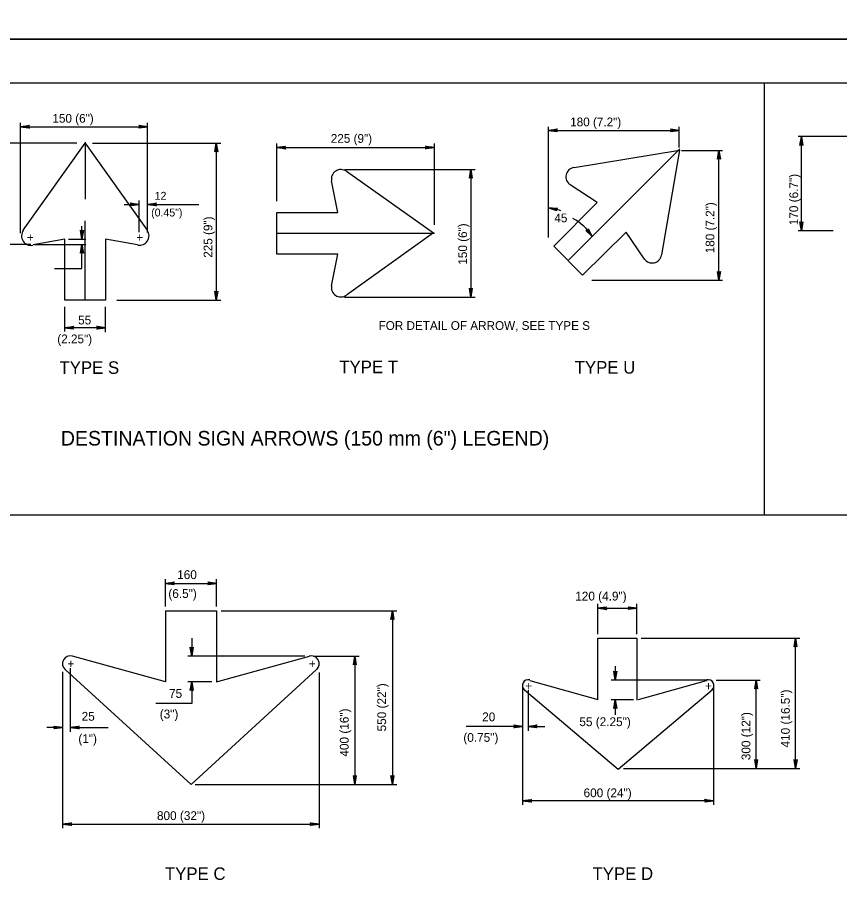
# Model space of a CAD drawing. Extents: x 637580 to 641849, y 297270 to 299646.
# Drawn here: x 641247.2 to 641528.9, y 298762.6 to 299059.1 of the extents above; entities that cross this region are included whole.
import ezdxf

# ---------------------------------------------------------------- set-up
doc = ezdxf.new("R2010")
doc.units = 0
for name, color, linetype in [('1', 7, 'Continuous'), ('2', 7, 'Continuous'), ('3', 7, 'Continuous'), ('XCS-GRID-HVGL', 7, 'Continuous')]:
    doc.layers.add(name, color=color, linetype=linetype)

# ---------------------------------------------------------------- blocks, each defined once
blk = doc.blocks.new('RARROW')
at = {"layer": '3'}
blk.add_lwpolyline([(-2.2695, 0.285), (-2.184875, 0.12075), (0, 0), (-2.2695, 0.285), (-2.38575, 0.384625), (0, 0), (-2.183125, -0.108), (-2.262875, -0.2705), (0, 0), (-2.38575, -0.379125), (-2.262875, -0.2705)], dxfattribs=at)

msp = doc.modelspace()

# ---------------------------------------------------------------- linework, layer by layer
at = {"layer": '1'}
msp.add_line((640984.31, 299036.63), (641770.31, 299036.63), dxfattribs=at)
for points in [[(641503.19, 298888.5), (641503.19, 299036.63)], [(641770.31, 298888.5), (640984.31, 298888.5)]]:
    msp.add_lwpolyline(points, dxfattribs=at)
at = {"layer": '2'}
for p, q in [((641248.31, 298985.13), (641248.31, 299023)), ((641248.31, 299021.63), (641291.81, 299021.63)), ((641291.81, 298985.38), (641291.81, 299023)), ((641429.19, 298983.63), (641429.19, 299021.63)), ((641473.94, 299014.5), (641473.94, 299021.63)), ((641429.19, 299020.38), (641473.94, 299020.38)), ((641549.69, 299018.25), (641514.69, 299018.25)), ((641515.81, 298986), (641515.81, 299018.25)), ((641267.56, 299016), (641235.44, 299016)), ((641249.19, 298986.13), (641270.44, 299016)), ((641270.44, 299016.38), (641270.44, 298996.75)), ((641270.44, 299016), (641270.44, 299016)), ((641270.44, 299016), (641291.69, 298986.13)), ((641272.94, 299016), (641316.94, 299016)), ((641315.33, 299016), (641315.33, 298962.25)), ((641336.06, 298996.13), (641336.06, 299015.88)), ((641390.06, 298988), (641390.06, 299015.88)), ((641336.06, 299014.5), (641390.06, 299014.5)), ((641435.94, 298975.75), (641474.19, 299014)), ((641437.94, 299007.63), (641474.06, 299013.63)), ((641474.06, 299013.63), (641467.94, 298977.75)), ((641474.69, 299013.5), (641488.81, 299013.5)), ((641487.56, 298969), (641487.56, 299013.5)), ((641359.31, 299007), (641404.06, 299007)), ((641359.94, 299006.38), (641389.81, 298985.25)), ((641402.56, 299007), (641402.56, 298963.25)), ((641356.94, 298992.25), (641354.81, 299003.13)), ((641445.81, 298995.63), (641436.56, 299001.75)), ((641283.81, 298995), (641288.94, 298995)), ((641288.94, 298985.5), (641288.94, 298996.38)), ((641291.81, 298995), (641309.32, 298995)), ((641430.94, 298980.75), (641445.81, 298995.63)), ((641336.06, 298978), (641336.06, 298992.25)), ((641336.06, 298992.25), (641356.94, 298992.25)), ((641270.44, 298962.25), (641270.44, 298989.38)), ((641269.31, 298983.13), (641269.31, 298987.5)), ((641336.06, 298985.13), (641390.06, 298985.13)), ((641389.81, 298985.25), (641359.94, 298963.88)), ((641455.81, 298985.5), (641440.81, 298970.75)), ((641462.06, 298976.25), (641455.81, 298985.5)), ((641526.69, 298986), (641514.69, 298986)), ((641263.44, 298983.13), (641252.56, 298981.13)), ((641263.44, 298983.13), (641263.44, 298983.13)), ((641263.44, 298962.25), (641263.44, 298983.13)), ((641264.69, 298983.13), (641270.69, 298983.13)), ((641277.44, 298983.13), (641277.44, 298983.13)), ((641288.31, 298981.13), (641277.44, 298983.13)), ((641277.44, 298983.13), (641277.44, 298962.25)), ((641251.81, 298981.25), (641235.44, 298981.25)), ((641253.06, 298981.25), (641270.69, 298981.25)), ((641269.31, 298973), (641269.31, 298981.25)), ((641440.81, 298970.75), (641430.94, 298980.75)), ((641356.94, 298978), (641336.06, 298978)), ((641354.81, 298967.13), (641356.94, 298978)), ((641259.94, 298973), (641269.31, 298973)), ((641444.06, 298969), (641488.81, 298969)), ((641263.44, 298962.25), (641263.44, 298962.25)), ((641277.44, 298962.25), (641263.44, 298962.25)), ((641277.44, 298962.25), (641277.44, 298962.25)), ((641281.31, 298962.25), (641316.94, 298962.25)), ((641359.31, 298963.25), (641404.06, 298963.25)), ((641263.44, 298951.5), (641263.44, 298959.88)), ((641277.44, 298951.25), (641277.44, 298959.88)), ((641277.44, 298952.75), (641263.44, 298952.75)), ((641297.94, 298857.25), (641297.94, 298866.63)), ((641315.44, 298857.25), (641315.44, 298866.63)), ((641297.94, 298865.13), (641315.44, 298865.13)), ((641446.06, 298847.75), (641446.06, 298858.13)), ((641459.44, 298847.75), (641459.44, 298858.13)), ((641297.94, 298855.75), (641297.94, 298855.75)), ((641297.94, 298855.75), (641297.94, 298831.38)), ((641297.94, 298855.75), (641315.44, 298855.75)), ((641315.44, 298855.75), (641315.44, 298855.75)), ((641315.44, 298855.75), (641315.44, 298831.38)), ((641317.06, 298855.75), (641377.19, 298855.75)), ((641375.69, 298855.75), (641375.69, 298796.25)), ((641446.04, 298856.63), (641459.42, 298856.63)), ((641306.94, 298846.38), (641306.94, 298840.25)), ((641446.06, 298846.38), (641446.06, 298846.38)), ((641446.06, 298825.38), (641446.06, 298846.38)), ((641446.06, 298846.38), (641459.44, 298846.38)), ((641459.44, 298846.38), (641459.44, 298846.38)), ((641459.44, 298846.38), (641459.44, 298825.13)), ((641460.94, 298846.38), (641515.31, 298846.38)), ((641513.81, 298801.75), (641513.81, 298846.38)), ((641297.94, 298831.38), (641266.06, 298840.25)), ((641345.69, 298840.25), (641305.56, 298840.25)), ((641315.44, 298831.38), (641347.31, 298840.25)), ((641348.69, 298840.25), (641364.31, 298840.25)), ((641362.81, 298840.25), (641362.81, 298796.25)), ((641263.44, 298839.63), (641263.44, 298839.63)), ((641349.81, 298839.63), (641349.81, 298839.63)), ((641452.06, 298836.75), (641452.06, 298832)), ((641262.69, 298834.88), (641262.69, 298781.25)), ((641262.69, 298834.63), (641262.69, 298814.25)), ((641306.69, 298796.25), (641263.56, 298835.63)), ((641265.31, 298836.13), (641265.31, 298814.25)), ((641306.69, 298796.25), (641349.69, 298835.63)), ((641350.56, 298834.63), (641350.56, 298781.25)), ((641297.94, 298831.38), (641297.94, 298831.38)), ((641313.81, 298831.38), (641305.56, 298831.38)), ((641306.69, 298831.38), (641306.69, 298831.38)), ((641306.69, 298831.38), (641306.69, 298831.38)), ((641306.94, 298831.38), (641306.94, 298823.96)), ((641315.44, 298831.38), (641315.44, 298831.38)), ((641420.31, 298832), (641420.31, 298832)), ((641422.81, 298831.88), (641446.06, 298825.38)), ((641483.69, 298832), (641450.69, 298832)), ((641460.06, 298825.38), (641483.31, 298831.88)), ((641485.06, 298832), (641485.06, 298832)), ((641485.69, 298832), (641485.69, 298832)), ((641486.56, 298832), (641501.69, 298832)), ((641500.31, 298801.75), (641500.31, 298832)), ((641420.31, 298830.63), (641420.31, 298814.63)), ((641420.31, 298830.63), (641420.31, 298789.25)), ((641453.06, 298801.38), (641420.94, 298828.5)), ((641422.19, 298828.5), (641422.19, 298814.63)), ((641485.19, 298828.5), (641453.06, 298801.38)), ((641485.69, 298830.63), (641485.69, 298789.25)), ((641446.31, 298825.25), (641446.31, 298825.25)), ((641458.31, 298825.25), (641450.69, 298825.25)), ((641452.06, 298825.25), (641452.06, 298820.13)), ((641453.06, 298825.25), (641453.06, 298825.25)), ((641459.69, 298825.25), (641459.69, 298825.25)), ((641306.94, 298823.96), (641294.64, 298823.96)), ((641420.31, 298816.13), (641400.94, 298816.13)), ((641422.19, 298816.13), (641427.94, 298816.13)), ((641262.69, 298815.75), (641257.31, 298815.75)), ((641265.31, 298815.75), (641278.31, 298815.75)), ((641452.81, 298801.75), (641452.81, 298801.75)), ((641452.81, 298801.75), (641452.81, 298801.75)), ((641454.81, 298801.75), (641501.69, 298801.75)), ((641454.81, 298801.75), (641515.31, 298801.75)), ((641306.69, 298796.25), (641306.69, 298796.25)), ((641306.69, 298796.25), (641306.69, 298796.25)), ((641308.06, 298796.25), (641377.19, 298796.25)), ((641308.06, 298796.25), (641364.31, 298796.25)), ((641485.69, 298790.63), (641420.31, 298790.63)), ((641262.69, 298782.63), (641350.56, 298782.63))]:
    msp.add_line(p, q, dxfattribs=at)
for centre, radius, start, end in [((641358, 299003.71), 3.24, 54.5839, 190.9563), ((641438.39, 299004.46), 3.24, 99.584, 235.9563), ((641427.08, 298975.31), 18.65, 70.1319, 83.4312), ((641428.5, 298973.89), 18.65, 32.7978, 61.1367), ((641251.86, 298984.22), 3.24, 144.584, 280.9563), ((641289.05, 298984.25), 3.24, 259.0428, 35.4161), ((641464.67, 298978.17), 3.24, 214.0428, 350.4161), ((641358, 298966.54), 3.24, 169.0428, 305.4161), ((641265.35, 298837.6), 2.7, 74.5414, 227.6502), ((641347.92, 298837.6), 2.7, 312.3498, 105.4586), ((641422.23, 298830.09), 2.02, 75.4325, 226.8476), ((641422.23, 298830.08), 2.02, 74.0715, 229.8431), ((641483.86, 298830.08), 2.02, 310.1569, 105.9285), ((641483.87, 298830.09), 2.02, 313.1524, 104.5675)]:
    msp.add_arc(centre, radius, start, end, dxfattribs=at)
at = {"layer": 'XCS-GRID-HVGL'}
for points in [[(640944.31, 299645.63), (641785.31, 299645.63), (641785.31, 299051.63), (640944.31, 299051.63)], [(640944.31, 299051.63), (641785.31, 299051.63), (641785.31, 298457.63), (640944.31, 298457.63)]]:
    msp.add_lwpolyline(points, close=True, dxfattribs=at)

# ---------------------------------------------------------------- block references
at = {"layer": '2', "xscale": 1.2574347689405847, "yscale": 1.3092961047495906}
for p, rotation in [((641248.31, 299021.63), 180), ((641429.19, 299020.38), 180), ((641515.81, 299018.25), 89.99999999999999), ((641315.33, 299016), 89.99999999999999), ((641336.06, 299014.5), 180), ((641487.56, 299013.5), 89.99999999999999), ((641402.56, 299007), 89.99999999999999), ((641291.81, 298995), 180), ((641429.21, 298993.83), 169.25034705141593), ((641515.81, 298986), -90.00000000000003), ((641269.31, 298983.13), -90.00000000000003), ((641444.18, 298983.99), -52.85020127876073), ((641269.31, 298981.25), 89.99999999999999), ((641487.56, 298969), -90.00000000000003), ((641315.33, 298962.25), -90.00000000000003), ((641402.56, 298963.25), -90.00000000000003), ((641263.44, 298952.75), 180), ((641297.94, 298865.13), 180), ((641375.69, 298855.75), 89.99999999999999), ((641446.04, 298856.63), 180), ((641513.81, 298846.38), 89.99999999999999), ((641306.94, 298840.25), -90.00000000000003), ((641362.81, 298840.25), 89.99999999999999), ((641452.06, 298832), -90.00000000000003), ((641306.94, 298831.38), 89.99999999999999), ((641500.31, 298832), 89.99999999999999), ((641452.06, 298825.25), 89.99999999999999), ((641265.31, 298815.75), 180), ((641422.19, 298816.13), 180), ((641500.31, 298801.75), -90.00000000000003), ((641513.81, 298801.75), -90.00000000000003), ((641362.81, 298796.25), -90.00000000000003), ((641375.69, 298796.25), -90.00000000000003), ((641420.31, 298790.63), 180), ((641262.69, 298782.63), 180)]:
    msp.add_blockref('RARROW', p, dxfattribs=dict(at, rotation=rotation))
for p in [(641291.81, 299021.63), (641473.94, 299020.38), (641390.06, 299014.5), (641288.94, 298995), (641277.44, 298952.75), (641315.44, 298865.13), (641459.42, 298856.63), (641262.69, 298815.75), (641420.31, 298816.13), (641485.69, 298790.63), (641350.56, 298782.63)]:
    msp.add_blockref('RARROW', p, dxfattribs=at)

# ---------------------------------------------------------------- texts
at = {"layer": '2'}
for s, height, p in [('150 (6")', 3, (641259.2, 299023.01)), ('180 (7.2")', 3, (641436.6, 299021.77)), ('225 (9")', 3, (641354.58, 299016.12)), (' 12', 2.699, (641293.23, 298996.61)), ('(0.45")', 2.699, (641293.03, 298990.88)), ('45', 3, (641431.19, 298988.88)), ('+', 3, (641250.44, 298982.25)), ('+', 3, (641287.94, 298982.25)), ('55', 3, (641268.01, 298953.88)), ('FOR DETAIL OF ARROW, SEE TYPE S', 3, (641370.94, 298952)), ('(2.25")', 3, (641260.87, 298947.42)), ('TYPE S', 4.3, (641261.61, 298936.94)), ('TYPE T', 4.3, (641357.49, 298937.17)), ('TYPE U', 4.3, (641438.15, 298937.02)), ('DESTINATION SIGN ARROWS (150 mm (6") LEGEND)', 5, (641262.1, 298912.38)), ('160', 3.022, (641301.94, 298866.62)), ('(6.5")', 3.022, (641298.91, 298860.15)), ('120 (4.9")', 3.022, (641438.32, 298859.27)), ('+', 3.02, (641264.31, 298836.13)), ('+', 3.02, (641347.06, 298836.13)), ('+', 3.02, (641421.19, 298828.5)), ('+', 3.02, (641482.81, 298828.5)), ('75', 3.022, (641299.15, 298825.91)), ('(3")', 3.022, (641295.97, 298818.86)), ('25 ', 3.022, (641269.21, 298818.07)), ('20 ', 3.022, (641406.44, 298817.88)), ('55 (2.25")', 3.022, (641439.74, 298816.22)), ('(1")', 3.022, (641268.08, 298810.43)), ('(0.75")', 3.022, (641399.99, 298810.84)), ('600 (24")', 3.022, (641441.18, 298791.86)), ('800 (32")', 3.022, (641295.01, 298784.03)), ('TYPE C', 4.3, (641297.74, 298763.51)), ('TYPE D', 4.3, (641444.24, 298763.51))]:
    msp.add_text(s, height=height, dxfattribs=at).set_placement(p)
for s, height, p in [('170 (6.7")', 3.022, (641514.7, 298987.86)), ('180 (7.2")', 3, (641486.01, 298978.26)), ('225 (9")', 3, (641314.01, 298976.73)), ('150 (6")', 3, (641401.26, 298974.37)), ('550 (22")', 3.022, (641373.53, 298814.41)), ('410 (16.5")', 3.0217, (641511.84, 298808.9)), ('400 (16")', 3.022, (641360.71, 298805.77)), ('300 (12")', 3.022, (641498.35, 298804.54))]:
    msp.add_text(s, height=height, rotation=90, dxfattribs=at).set_placement(p)

doc.saveas('drawing.dxf')
